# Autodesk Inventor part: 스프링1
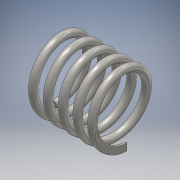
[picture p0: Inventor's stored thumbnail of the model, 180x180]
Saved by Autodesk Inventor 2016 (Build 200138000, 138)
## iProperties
Created: 2019-11
Part Number: 스프링1
Material: 스테인레스 스틸
Document SubType Name: Modeling
Designer: user
Density: 8 g/cm^3
Appearance: 반연마
Mass: 6.57252 g
Surface Area: 16.7217 cm^2
Volume: 0.821565 cm^3
Author: user
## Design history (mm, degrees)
sketch "스케치2"
  geometry: L1 (0, 0)-(20.5, 0); L2 (20.5, 0)-(20.5, -8.5); L3 (20.5, -8.5)-(0, -8.5); L4 (0, -8.5)-(0, 0); C1 r 1 at (0, -8.5)
  constraints: 8 end point, 2 parallel, 1 centre point, 1 coincident, 1 horizontal, 1 perpendicular
  dimensions: "d0" = 17 diameter of L3 L1; "d1" = 20.5 distance between parallel lines of L4 L2 (derived); "d2" = 2 diameter of C1
feature "코일1" sketch "스케치2" pitch "d3" = 10; turns "d5" = 5; dims "d4" = 20.5 (= d1), "d6" = 0, angle "d7" = 90 deg, angle "d8" = 90 deg, "d9" = 0, "d10" = 0
sketch "스케치3"
  geometry: L1 (0, -15)-(-20.5, -15); L2 (-20.5, -15)-(-20.5, 15); L3 (-20.5, 15)-(0, 15); L4 (0, 15)-(0, -15); 2 further points
  constraints: 8 end point, 2 parallel, 1 coincident, 1 horizontal, 1 midpoint, 1 perpendicular
  dimensions: "d11" = 20.5 distance of L2.end L3.end (= d1); "d12" = 30 distance of L1.end L2.end
extrude "돌출1" sketch "스케치3" stored distance "d13" = 42.75; taper "d14" = 0 deg
node "솔리드1"
